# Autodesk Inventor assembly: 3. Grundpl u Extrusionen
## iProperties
Created: 2011-05
Part Number: 3. Grundpl u Extrusionen
Document SubType Name: Assembly
Designer: Lorenz Humpel
Author: Lorenz Humpel
